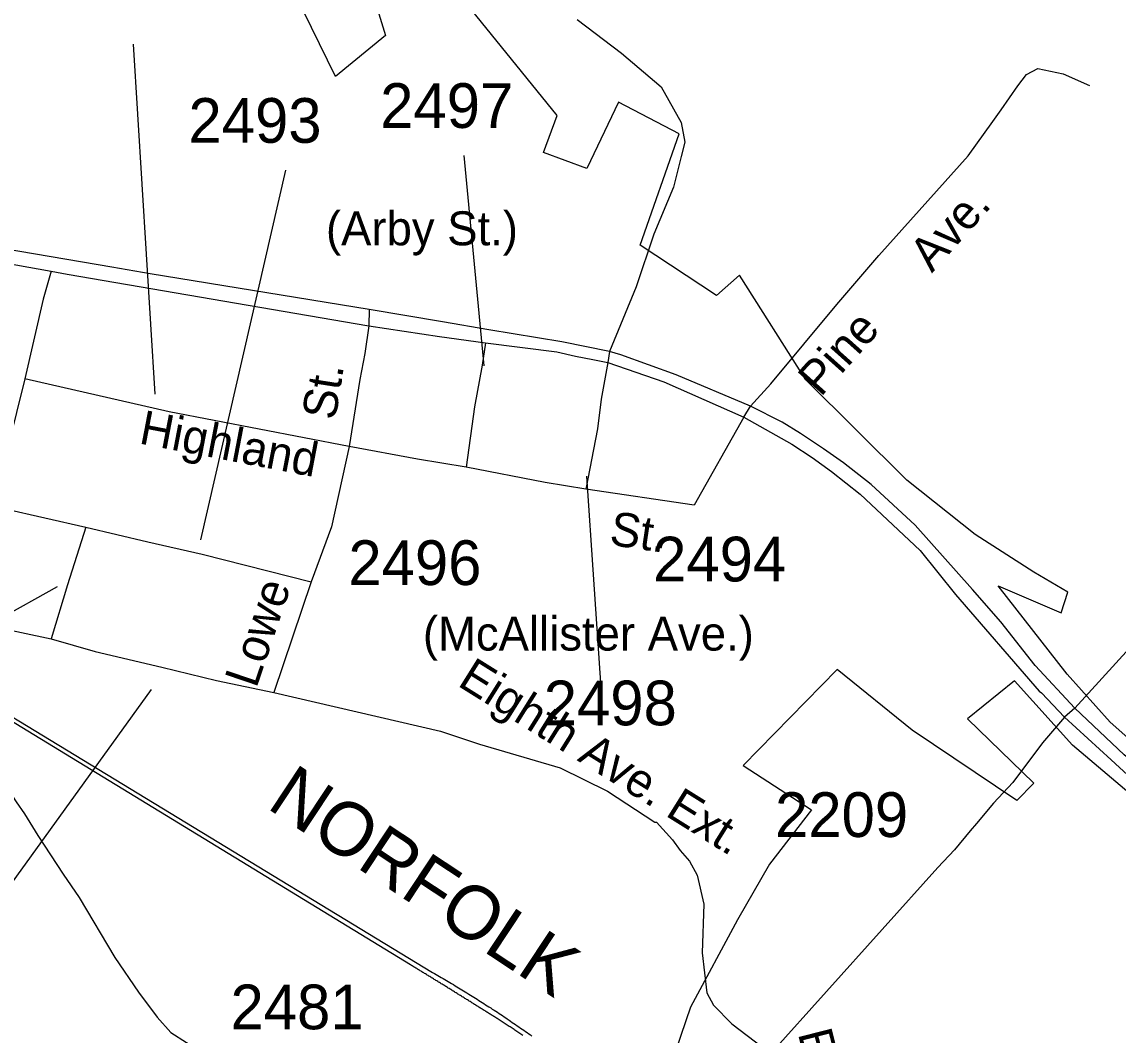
# Model space of a CAD drawing. Extents: x 1364363 to 1407445, y 538563 to 573342.
# Drawn here: x 1376290 to 1379352, y 551955 to 554787 of the extents above; entities that cross this region are included whole.
import ezdxf

# ---------------------------------------------------------------- set-up
doc = ezdxf.new("R2010")
doc.units = 0
for name, color, linetype in [('Exist Boundary Political City Limit New', 7, 'Continuous'), ('Exist Railroad Mainline', 7, 'Continuous'), ('Exist Railroad Mainline Label', 7, 'Continuous'), ('Exist Railroad Siding', 7, 'Continuous'), ('Exist Road Primary US Divided Attributed', 7, 'Continuous'), ('Exist Road Secondary Type 51 Attributed', 7, 'Continuous'), ('Exist Road Secondary Type 51 Label', 7, 'Continuous'), ('Exist Road Secondary Type 51 Number Label', 7, 'Continuous')]:
    doc.layers.add(name, color=color, linetype=linetype)

msp = doc.modelspace()

# ---------------------------------------------------------------- linework, layer by layer
at = {"layer": 'Exist Boundary Political City Limit New'}
for points in [[(1377154.8, 555239.6), (1377305.8, 554748.8), (1377166, 554634.2), (1376876.8, 555225.4)], [(1379420.2, 552749.8), (1379330.5, 552830.2), (1379209.8, 552964.1), (1379017.4, 553210.5), (1379193.5, 553134.9), (1379212.1, 553192.7), (1379117.2, 553248.8), (1378953.2, 553354.1), (1378762.5, 553506.2), (1378480.1, 553786.2), (1378295, 554078.8), (1378230.5, 554022.2), (1378017, 554163.4), (1378125.8, 554474), (1377956.5, 554562.8), (1377867.9, 554377.2), (1377746.9, 554422), (1377784.9, 554525.8), (1377207.1, 555240.4)], [(1379430.8, 552591.1), (1379225, 552765.4), (1379063.2, 552945.7), (1378932, 552839), (1379117.1, 552658.9), (1379069.2, 552610.4), (1378777.1, 552807.1), (1378567.8, 552977.1), (1378304.9, 552708.4), (1378496, 552584.8), (1378378.8, 552433.1), (1378289.2, 552277.4), (1378157.8, 552033.2), (1378103, 551871.7)]]:
    msp.add_lwpolyline(points, dxfattribs=at)
at = {"layer": 'Exist Railroad Mainline'}
for points in [[(1377375.6, 552151.4), (1375413.5, 553349.2), (1374539.8, 553882.6)], [(1377617.6, 552001.1), (1377615.3, 552002.6), (1377612.8, 552004.1), (1377610.3, 552005.7), (1377607.9, 552007.2), (1377605.5, 552008.8), (1377603.2, 552010.3), (1377600.6, 552011.8), (1377598.2, 552013.4), (1377595.8, 552014.9), (1377593.4, 552016.5), (1377590.9, 552018), (1377588.5, 552019.5), (1377586, 552021.1), (1377583.7, 552022.6), (1377581.1, 552024.1), (1377578.8, 552025.6), (1377576.3, 552027.2), (1377573.8, 552028.7), (1377571.4, 552030.2), (1377569, 552031.7), (1377566.5, 552033.3), (1377564.1, 552034.8), (1377561.6, 552036.4), (1377559.3, 552037.9), (1377556.7, 552039.4), (1377554.4, 552041), (1377551.9, 552042.5), (1377549.5, 552044), (1377547, 552045.6), (1377544.6, 552047.1), (1377542.2, 552048.6), (1377539.8, 552050.1), (1377537.2, 552051.6), (1377534.9, 552053.2), (1377532.4, 552054.7), (1377530, 552056.2), (1377527.5, 552057.7), (1377525.1, 552059.3), (1377522.7, 552060.8), (1377520.1, 552062.3), (1377517.8, 552063.8), (1377515.3, 552065.4), (1377512.8, 552066.9), (1377510.4, 552068.4), (1377508, 552069.9), (1377505.5, 552071.4), (1377503.1, 552073), (1377500.6, 552074.5), (1377498.3, 552076), (1377495.7, 552077.5), (1377493.2, 552079.1), (1377490.9, 552080.5), (1377488.3, 552082.1), (1377486, 552083.6), (1377483.5, 552085.1), (1377481.1, 552086.6), (1377478.6, 552088.1), (1377476.1, 552089.6), (1377473.8, 552091.2), (1377471.2, 552092.7), (1377468.8, 552094.2), (1377466.4, 552095.7), (1377463.9, 552097.2), (1377461.5, 552098.7), (1377459, 552100.3), (1377456.6, 552101.8), (1377454.1, 552103.2), (1377451.6, 552104.7), (1377449.3, 552106.3), (1377446.7, 552107.8), (1377444.3, 552109.3), (1377441.9, 552110.8), (1377439.4, 552112.3), (1377437, 552113.8), (1377434.5, 552115.3), (1377432.1, 552116.9), (1377429.6, 552118.4), (1377427.1, 552119.9), (1377424.8, 552121.4), (1377422.3, 552122.9), (1377419.8, 552124.4), (1377417.4, 552125.9), (1377414.9, 552127.4), (1377412.5, 552128.9), (1377410, 552130.4), (1377407.5, 552131.9), (1377405.1, 552133.4), (1377402.6, 552134.9), (1377400.2, 552136.4), (1377397.8, 552137.8), (1377395.2, 552139.4), (1377392.8, 552140.9), (1377390.4, 552142.4), (1377387.8, 552143.9), (1377385.5, 552145.4), (1377383, 552146.9), (1377380.5, 552148.4), (1377378.1, 552149.9), (1377375.6, 552151.4)], [(1377689.3, 551953.8), (1377686.5, 551955.7), (1377683.7, 551957.6), (1377681, 551959.4), (1377678.2, 551961.2), (1377675.6, 551963), (1377672.9, 551964.9), (1377670.1, 551966.7), (1377667.3, 551968.6), (1377664.7, 551970.4), (1377661.9, 551972.3), (1377659.1, 551974.1), (1377656.4, 551976), (1377653.6, 551977.8), (1377650.8, 551979.5), (1377648.2, 551981.4), (1377645.4, 551983.2), (1377642.6, 551985), (1377639.9, 551986.8), (1377637.1, 551988.6), (1377634.4, 551990.4), (1377631.5, 551992.2), (1377628.8, 551994), (1377626, 551995.7), (1377623.2, 551997.5), (1377620.5, 551999.3), (1377617.6, 552001.1)]]:
    msp.add_lwpolyline(points, dxfattribs=at)
at = {"layer": 'Exist Railroad Siding'}
for points in [[(1374539.4, 553898.1), (1375118.3, 553540.2), (1375881.2, 553076.7), (1377437.4, 552130)], [(1377437.4, 552130), (1377442.3, 552127.1), (1377447, 552124.4), (1377451.8, 552121.5), (1377456.7, 552118.7), (1377461.5, 552116), (1377466.4, 552113.1), (1377471.2, 552110.3), (1377476, 552107.5), (1377480.8, 552104.7), (1377485.7, 552101.8), (1377490.4, 552098.9), (1377495.3, 552096.1), (1377500, 552093.2), (1377504.7, 552090.3), (1377509.7, 552087.5), (1377514.4, 552084.6), (1377519.1, 552081.6), (1377523.9, 552078.7), (1377528.6, 552075.8), (1377533.3, 552072.9), (1377538.2, 552069.9), (1377542.9, 552067), (1377547.6, 552064.1), (1377552.4, 552061.1), (1377557.1, 552058.1), (1377561.8, 552055.1), (1377566.7, 552052.2), (1377571.3, 552049.2), (1377576, 552046.2), (1377580.7, 552043.1), (1377585.4, 552040.1), (1377590.1, 552037.1), (1377594.7, 552034), (1377599.5, 552031.1), (1377604.1, 552028), (1377608.9, 552024.9), (1377613.5, 552021.9), (1377618.1, 552018.8), (1377622.8, 552015.7), (1377627.5, 552012.6), (1377632.2, 552009.5), (1377636.8, 552006.5), (1377641.4, 552003.3), (1377646, 552000.2), (1377650.7, 551997.1), (1377655.2, 551994), (1377659.9, 551990.7), (1377664.5, 551987.6), (1377669.1, 551984.5), (1377673.8, 551981.3), (1377678.4, 551978.1), (1377682.9, 551974.9), (1377687.5, 551971.8), (1377692.1, 551968.6), (1377696.7, 551965.3), (1377701.3, 551962.1), (1377705.8, 551958.9), (1377710.4, 551955.7), (1377714.9, 551952.4)]]:
    msp.add_lwpolyline(points, dxfattribs=at)
at = {"layer": 'Exist Road Primary US Divided Attributed'}
for points in [[(1377259.9, 553983.6), (1376648.6, 554082.9), (1376540.9, 554101.7), (1376063.9, 554182.9), (1375889.4, 554215.8)], [(1376037.3, 554147.2), (1376137.2, 554132.1), (1376371.8, 554090.8)], [(1376371.8, 554090.8), (1376415.9, 554082.2), (1377258.8, 553937.5)], [(1377931.1, 553865.5), (1377798.3, 553892.6), (1377594.4, 553925.9), (1377465.2, 553948.7), (1377259.9, 553983.6)], [(1377258.8, 553937.5), (1377456.3, 553907.6), (1377584.6, 553890.4)], [(1377584.6, 553890.4), (1377784, 553865), (1377836.7, 553852.8), (1377884.7, 553843.8), (1377926.7, 553834.6)], [(1378325.1, 553712.8), (1378118.1, 553800.6), (1377962.7, 553856.4), (1377931.1, 553865.5)], [(1377926.7, 553834.6), (1378083.4, 553780.7), (1378306.7, 553682.5)], [(1379231.5, 552868.9), (1379121.1, 552988.4), (1379025.1, 553109.9), (1378945.2, 553200.5), (1378785.9, 553380.7), (1378662.1, 553493.9), (1378585.2, 553554.2), (1378529.4, 553593.8), (1378464.8, 553636.4), (1378413.5, 553668.1), (1378325.1, 553712.8)], [(1378306.7, 553682.5), (1378440.7, 553607.1), (1378497.7, 553569.6), (1378552, 553530.1), (1378632, 553466.7), (1378799.4, 553309.7), (1378898.4, 553186.9), (1379132.2, 552916.7), (1379138.3, 552912.2), (1379202.8, 552844.1)], [(1381125.6, 552035.3), (1380934.6, 552096), (1380642.8, 552176.1), (1380369.8, 552273.8), (1380183.4, 552330.8), (1380079.2, 552348.8), (1379929.3, 552399.7), (1379866.4, 552420.7), (1379779.5, 552462.7), (1379722.6, 552489.7), (1379644.7, 552537.7), (1379527.8, 552612.6), (1379503.8, 552630.6), (1379369, 552738.5), (1379231.5, 552868.9)], [(1379202.8, 552844.1), (1379332.7, 552724.3), (1379390.5, 552671.5), (1379438.4, 552626.5), (1379483.4, 552590.6), (1379612.2, 552500.6), (1379720.1, 552443.7), (1379822, 552398.7), (1379938.8, 552353.7), (1380034.7, 552323.7), (1380083.1, 552316.1), (1380250.9, 552268.2), (1380433.3, 552209.8), (1380634, 552146.3), (1380798.3, 552110.5), (1380938.3, 552069.4), (1381083.1, 552026), (1381119.4, 552012.7)]]:
    msp.add_lwpolyline(points, dxfattribs=at)
at = {"layer": 'Exist Road Secondary Type 51 Attributed'}
msp.add_line((1377098.4, 553221.8), (1376993.3, 552912.6), dxfattribs=at)
for points in [[(1377840.7, 554794), (1377964.9, 554699.3), (1378076.2, 554605.8), (1378131.7, 554505.8), (1378142.2, 554450.7), (1378131.7, 554411.3), (1378110.7, 554324.7), (1378055.6, 554193.4), (1378005.8, 554046.4), (1377931.1, 553865.5)], [(1378325.1, 553712.8), (1378382.4, 553775.6), (1378566.8, 553997.6), (1378683.6, 554133.9), (1378933.4, 554413.1), (1379002.6, 554508.9), (1379026, 554541.3), (1379072.5, 554608.8), (1379096.6, 554640.5), (1379128.3, 554657.1), (1379199.2, 554642), (1379272.9, 554609.7)], [(1376371.8, 554090.8), (1376349.5, 554012.3), (1376297.8, 553789.8)], [(1374117.7, 554009.2), (1374432.9, 553822.1), (1375122.9, 553398.4), (1375350, 553268.5), (1375719.3, 553065.2), (1376079.5, 552847.5), (1376150.3, 552780.5), (1376223.8, 552683.4), (1376273.6, 552607.2), (1376297.2, 552573.1), (1376334, 552512.7), (1376404.8, 552405.1), (1376449.4, 552339.5), (1376549.7, 552171.6), (1376615.6, 552074.7), (1376667.6, 552004.8), (1376705.6, 551962.2), (1376837.6, 551878.6)], [(1377259.9, 553983.6), (1377258.8, 553937.5)], [(1377258.8, 553937.5), (1377247.8, 553860.4), (1377233.8, 553787.8), (1377204.2, 553600.6)], [(1377584.6, 553890.4), (1377575.7, 553828), (1377554.6, 553710.9), (1377531.3, 553542.1)], [(1377931.1, 553865.5), (1377926.7, 553834.6)], [(1377926.7, 553834.6), (1377908.4, 553732.7), (1377897.9, 553649.6), (1377865.6, 553480.8)], [(1376297.8, 553789.8), (1376251.5, 553601.3), (1376217.2, 553470.2), (1376224.4, 553443.3), (1376239.6, 553426.6), (1376468.1, 553375.1)], [(1377204.2, 553600.6), (1376701.3, 553697), (1376297.8, 553789.8)], [(1378306.7, 553682.5), (1378325.1, 553712.8)], [(1378306.7, 553682.5), (1378168.2, 553436.5), (1377865.6, 553480.8)], [(1377204.2, 553600.6), (1377154.8, 553375.4), (1377098.4, 553221.8)], [(1377531.3, 553542.1), (1377395, 553564.6), (1377204.2, 553600.6)], [(1377865.6, 553480.8), (1377751.8, 553499.2), (1377531.3, 553542.1)], [(1376468.1, 553375.1), (1376417, 553213.9), (1376371.4, 553062.5)], [(1376468.1, 553375.1), (1376641.8, 553334.1), (1376793.1, 553299), (1377098.4, 553221.8)], [(1375844.1, 553185.7), (1376218.1, 553094.9), (1376371.4, 553062.5)], [(1379460.5, 553120.6), (1379231.5, 552868.9)], [(1376371.4, 553062.5), (1376494.3, 553027), (1376680.5, 552983.1), (1376833.8, 552946), (1376993.3, 552912.6)], [(1376993.3, 552912.6), (1377459.3, 552804.9), (1377568.6, 552768.7), (1377793.2, 552702), (1377926, 552637.1), (1378058.3, 552550.4), (1378062.4, 552550.6), (1378107.2, 552501), (1378128.6, 552470.7), (1378155.3, 552441.4), (1378176.3, 552402), (1378194.7, 552320.6), (1378190.3, 552184.7), (1378203.1, 552073), (1378222.3, 552038.9), (1378273.4, 551986.2), (1378382.3, 551904.1)], [(1379231.5, 552868.9), (1379202.8, 552844.1)], [(1379202.8, 552844.1), (1379140.8, 552771.6), (1379057.9, 552661.3), (1379004.4, 552603.6), (1378957.1, 552546.9), (1378939.3, 552525.9), (1378895.2, 552473), (1378849.1, 552423.8), (1378382.3, 551904.1)]]:
    msp.add_lwpolyline(points, dxfattribs=at)
at = {"layer": 'Exist Road Secondary Type 51 Number Label'}
for p, q in [((1376662.1, 553747), (1376601.3, 554724.8)), ((1377581.3, 553825.5), (1377525.2, 554414)), ((1376789.8, 553339.5), (1377027.5, 554372.3)), ((1377867.1, 553517.2), (1377906.4, 552939.9)), ((1376388.1, 553208.3), (1374740.5, 552282)), ((1376650.5, 552921.4), (1376101.2, 552159))]:
    msp.add_line(p, q, dxfattribs=at)

# ---------------------------------------------------------------- texts
at = {"layer": 'Exist Railroad Mainline Label'}
msp.add_text('        NORFOLK', height=150, rotation=326.5085, dxfattribs=at).set_placement((1376598.5, 552837.7))
at = {"layer": 'Exist Road Secondary Type 51 Label'}
for s, rotation, p in [('Pine      Ave.', 48.1703, (1378521.4, 553736.5)), ('St.', 81.0358, (1377165.6, 553671.7)), ('Highland', 349.1469, (1376614.2, 553609.2)), ('St.', 351.6665, (1377928.5, 553325.9)), ('Lowe', 71.2296, (1376944.6, 552922.3)), ('Eighth Ave. Ext.', 327.9758, (1377503.7, 552933.5)), ('Eighth Ave.', 284.3065, (1378457.4, 551959.8))]:
    msp.add_text(s, height=95, rotation=rotation, dxfattribs=at).set_placement(p)
for s, p in [('(Arby St.)', (1377139.3, 554162.6)), ('(McAllister Ave.)', (1377410.1, 553029.9))]:
    msp.add_text(s, height=95, dxfattribs=at).set_placement(p)
at = {"layer": 'Exist Road Secondary Type 51 Number Label'}
for s, p in [('2497', (1377290.8, 554490.7)), ('2493', (1376755.2, 554449.1)), ('2496', (1377201.9, 553213)), ('2494', (1378053.3, 553223.1)), ('2498', (1377747.7, 552820.9)), ('2209', (1378394, 552508.8)), ('2481', (1376872.6, 551971.3))]:
    msp.add_text(s, height=125, dxfattribs=at).set_placement(p)

doc.saveas('drawing.dxf')
